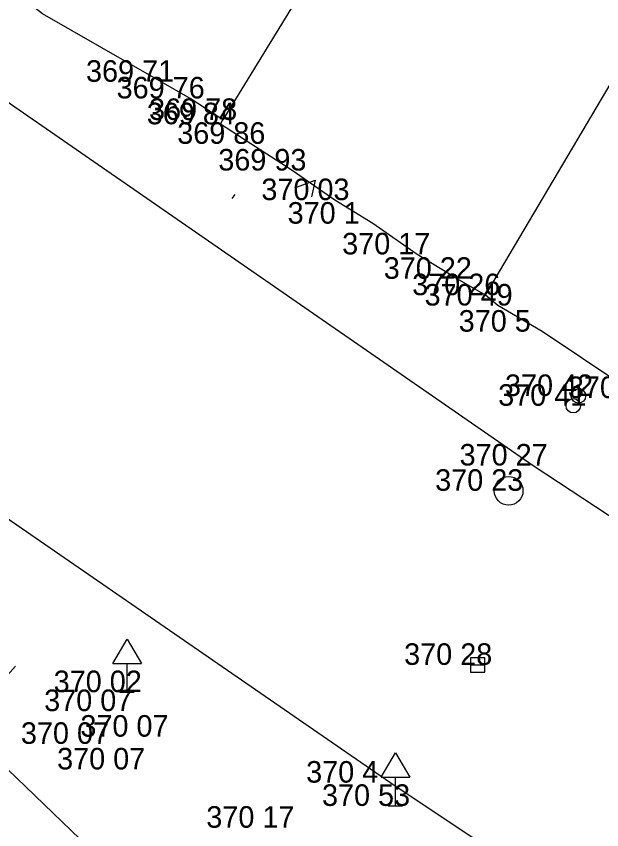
# Model space of a CAD drawing. Extents: x -688316 to -688024, y -973785 to -973591.
# Drawn here: x -688090.23 to -688069.85, y -973719.16 to -973690.84 of the extents above; entities that cross this region are included whole.
import ezdxf

# ---------------------------------------------------------------- set-up
doc = ezdxf.new("R2010")
doc.units = 0
for name, color, linetype in [('Vrstva 10', 7, 'Continuous'), ('Vrstva 27', 7, 'Continuous'), ('Vrstva 28_Verejne osvetleni', 7, 'Continuous'), ('Vrstva 3', 7, 'Continuous'), ('Vrstva 31', 7, 'Continuous'), ('Vrstva 34', 7, 'Continuous'), ('Vrstva 5', 7, 'Continuous'), ('Vrstva 50_telekomunikace cetin WMS', 7, 'Continuous'), ('Vrstva 6', 7, 'Continuous')]:
    doc.layers.add(name, color=color, linetype=linetype)

# ---------------------------------------------------------------- blocks, each defined once
blk = doc.blocks.new('DZ')
at = {"layer": 'Vrstva 34'}
for p, q in [((-5, 10), (0, 18.5)), ((0, 18.5), (5, 10)), ((-5, 10), (5, 10)), ((0, 0), (0, 10)), ((-2.49, 0), (2.49, 0))]:
    blk.add_line(p, q, dxfattribs=at)
blk = doc.blocks.new('VP')
at = {"layer": 'Vrstva 27'}
blk.add_line((-2.5, 0), (2.5, 0), dxfattribs=at)
blk.add_lwpolyline([(-2.5, -2.5), (2.5, -2.5), (2.5, 2.5), (-2.5, 2.5)], close=True, dxfattribs=at)
blk = doc.blocks.new('SV')
at = {"layer": 'Vrstva 28_Verejne osvetleni'}
blk.add_circle((0, 0), 2.5, dxfattribs=at)
blk = doc.blocks.new('SP')
at = {"layer": 'Vrstva 31'}
blk.add_circle((0, 0), 2.5, dxfattribs=at)
blk = doc.blocks.new('SAK')
at = {"layer": 'Vrstva 27'}
blk.add_circle((0, 0), 5, dxfattribs=at)

msp = doc.modelspace()

# ---------------------------------------------------------------- linework, layer by layer
at = {"layer": 'Vrstva 10'}
for p, q in [((-688093.66, -973691.65), (-688072.24, -973706.48)), ((-688077.23, -973717.52), (-688096.68, -973704.1)), ((-688072.24, -973706.48), (-688062.29, -973713.03)), ((-688069.37, -973722.73), (-688077.23, -973717.52))]:
    msp.add_line(p, q, dxfattribs=at)
at = {"layer": 'Vrstva 28_Verejne osvetleni'}
for p, q in [((-688080.528, -973696.814), (-688079.823, -973696.54)), ((-688079.823, -973696.54), (-688079.952, -973697.121))]:
    msp.add_line(p, q, dxfattribs=at)
at = {"layer": 'Vrstva 3'}
msp.add_lwpolyline([(-688071.97, -973725.53), (-688075.592, -973732.953), (-688087.068, -973720.398), (-688092.114, -973715.537), (-688090.26, -973713.47)], dxfattribs=at)
msp.add_lwpolyline([(-688071.97, -973725.53), (-688075.592, -973732.953), (-688087.068, -973720.398), (-688092.114, -973715.537), (-688090.26, -973713.47)], dxfattribs=at)
msp.add_lwpolyline([(-688071.97, -973725.53), (-688075.592, -973732.953), (-688087.068, -973720.398), (-688092.114, -973715.537), (-688090.26, -973713.47)], dxfattribs=at)
msp.add_lwpolyline([(-688071.97, -973725.53), (-688075.592, -973732.953), (-688087.068, -973720.398), (-688092.114, -973715.537), (-688090.26, -973713.47)], dxfattribs=at)
at = {"layer": 'Vrstva 5'}
for p, q in [((-688075.97, -973682.88), (-688083.04, -973694.45)), ((-688073.89, -973700.55), (-688068.56, -973691.52)), ((-688083.04, -973694.45), (-688084.17, -973693.7)), ((-688079.14, -973697.24), (-688080.63, -973696.21)), ((-688076.27, -973699.13), (-688077.82, -973698.06)), ((-688073.89, -973700.55), (-688074.88, -973699.98)), ((-688073.46, -973700.91), (-688073.89, -973700.55)), ((-688068.47, -973704.13), (-688071.92, -973701.82))]:
    msp.add_line(p, q, dxfattribs=at)
for points in [[(-688085.18, -973693.12), (-688089.31, -973690.76), (-688089.67, -973690.48), (-688089.75, -973690.26), (-688089.7, -973690), (-688088.85, -973688.72), (-688090.74, -973687.47), (-688091.1, -973687.21), (-688091.3, -973686.83), (-688085.88, -973677.49)], [(-688082.06, -973695.28), (-688083.12, -973694.6), (-688083.04, -973694.45)]]:
    msp.add_lwpolyline(points, dxfattribs=at)
at = {"layer": 'Vrstva 50_telekomunikace cetin WMS'}
msp.add_lwpolyline([(-688082.71, -973697.18), (-688082.61, -973697.05)], dxfattribs=at)
at = {"layer": 'Vrstva 6'}
for p, q in [((-688084.17, -973693.7), (-688085.18, -973693.12)), ((-688080.63, -973696.21), (-688082.06, -973695.28)), ((-688077.82, -973698.06), (-688079.14, -973697.24)), ((-688074.88, -973699.98), (-688076.27, -973699.13)), ((-688071.92, -973701.82), (-688073.46, -973700.91))]:
    msp.add_line(p, q, dxfattribs=at)

# ---------------------------------------------------------------- block references
at = {"layer": 'Vrstva 27', "xscale": 0.1, "yscale": 0.10000000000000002}
for name, p in [('SAK', (-688073.09, -973707.36)), ('VP', (-688074.17, -973713.42))]:
    msp.add_blockref(name, p, dxfattribs=at)
at = {"layer": 'Vrstva 28_Verejne osvetleni', "xscale": 0.1, "yscale": 0.10000000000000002}
msp.add_blockref('SV', (-688070.84, -973704.4), dxfattribs=at)
at = {"layer": 'Vrstva 31', "xscale": 0.1, "yscale": 0.10000000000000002}
msp.add_blockref('SP', (-688070.66, -973704.06), dxfattribs=at)
at = {"layer": 'Vrstva 34', "xscale": 0.1, "yscale": 0.10000000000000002}
for p in [(-688086.37, -973714.37), (-688086.37, -973714.37), (-688086.37, -973714.37), (-688086.37, -973714.37), (-688077.03, -973718.33), (-688077.03, -973718.33), (-688077.03, -973718.33), (-688077.03, -973718.33)]:
    msp.add_blockref('DZ', p, dxfattribs=at)

# ---------------------------------------------------------------- texts
at = {"layer": 'Vrstva 3'}
for s, p in [('369 71 ', (-688087.801, -973693.12)), ('369 71 ', (-688087.801, -973693.12)), ('369 71 ', (-688087.801, -973693.12)), ('369 71 ', (-688087.801, -973693.12)), ('369 71 ', (-688087.801, -973693.12)), ('369 71 ', (-688087.801, -973693.12)), ('369 71 ', (-688087.801, -973693.12)), ('369 76 ', (-688086.736, -973693.7)), ('369 76 ', (-688086.736, -973693.7)), ('369 76 ', (-688086.736, -973693.7)), ('369 76 ', (-688086.736, -973693.7)), ('369 76 ', (-688086.736, -973693.7)), ('369 76 ', (-688086.736, -973693.7)), ('369 76 ', (-688086.736, -973693.7)), ('369 78 ', (-688085.606, -973694.45)), ('369 78 ', (-688085.606, -973694.45)), ('369 78 ', (-688085.606, -973694.45)), ('369 78 ', (-688085.606, -973694.45)), ('369 78 ', (-688085.606, -973694.45)), ('369 78 ', (-688085.606, -973694.45)), ('369 78 ', (-688085.606, -973694.45)), ('369 84 ', (-688085.686, -973694.6)), ('369 84 ', (-688085.686, -973694.6)), ('369 84 ', (-688085.686, -973694.6)), ('369 84 ', (-688085.686, -973694.6)), ('369 84 ', (-688085.686, -973694.6)), ('369 84 ', (-688085.686, -973694.6)), ('369 84 ', (-688085.686, -973694.6)), ('369 86 ', (-688084.626, -973695.28)), ('369 86 ', (-688084.626, -973695.28)), ('369 86 ', (-688084.626, -973695.28)), ('369 86 ', (-688084.626, -973695.28)), ('369 86 ', (-688084.626, -973695.28)), ('369 86 ', (-688084.626, -973695.28)), ('369 86 ', (-688084.626, -973695.28)), ('369 93 ', (-688083.196, -973696.21)), ('369 93 ', (-688083.196, -973696.21)), ('369 93 ', (-688083.196, -973696.21)), ('369 93 ', (-688083.196, -973696.21)), ('369 93 ', (-688083.196, -973696.21)), ('369 93 ', (-688083.196, -973696.21)), ('369 93 ', (-688083.196, -973696.21)), ('370 03 ', (-688081.697, -973697.24)), ('370 03 ', (-688081.697, -973697.24)), ('370 03 ', (-688081.697, -973697.24)), ('370 03 ', (-688081.697, -973697.24)), ('370 03 ', (-688081.697, -973697.24)), ('370 03 ', (-688081.697, -973697.24)), ('370 03 ', (-688081.697, -973697.24)), ('370 1  ', (-688080.784, -973698.06)), ('370 1  ', (-688080.784, -973698.06)), ('370 1  ', (-688080.784, -973698.06)), ('370 1  ', (-688080.784, -973698.06)), ('370 1  ', (-688080.784, -973698.06)), ('370 1  ', (-688080.784, -973698.06)), ('370 1  ', (-688080.784, -973698.06)), ('370 17 ', (-688078.883, -973699.13)), ('370 17 ', (-688078.883, -973699.13)), ('370 17 ', (-688078.883, -973699.13)), ('370 17 ', (-688078.883, -973699.13)), ('370 17 ', (-688078.883, -973699.13)), ('370 17 ', (-688078.883, -973699.13)), ('370 17 ', (-688078.883, -973699.13)), ('370 22 ', (-688077.437, -973699.98)), ('370 22 ', (-688077.437, -973699.98)), ('370 22 ', (-688077.437, -973699.98)), ('370 22 ', (-688077.437, -973699.98)), ('370 22 ', (-688077.437, -973699.98)), ('370 22 ', (-688077.437, -973699.98)), ('370 22 ', (-688077.437, -973699.98)), ('370 26 ', (-688076.447, -973700.55)), ('370 26 ', (-688076.447, -973700.55)), ('370 26 ', (-688076.447, -973700.55)), ('370 26 ', (-688076.447, -973700.55)), ('370 26 ', (-688076.447, -973700.55)), ('370 26 ', (-688076.447, -973700.55)), ('370 26 ', (-688076.447, -973700.55)), ('370 49 ', (-688076.017, -973700.91)), ('370 49 ', (-688076.017, -973700.91)), ('370 49 ', (-688076.017, -973700.91)), ('370 49 ', (-688076.017, -973700.91)), ('370 49 ', (-688076.017, -973700.91)), ('370 49 ', (-688076.017, -973700.91)), ('370 49 ', (-688076.017, -973700.91)), ('370 5  ', (-688074.828, -973701.82)), ('370 5  ', (-688074.828, -973701.82)), ('370 5  ', (-688074.828, -973701.82)), ('370 5  ', (-688074.828, -973701.82)), ('370 5  ', (-688074.828, -973701.82)), ('370 5  ', (-688074.828, -973701.82)), ('370 5  ', (-688074.828, -973701.82)), ('370 42 ', (-688073.217, -973704.06)), ('370 42 ', (-688073.217, -973704.06)), ('370 42 ', (-688073.217, -973704.06)), ('370 42 ', (-688073.217, -973704.06)), ('370 42 ', (-688073.217, -973704.06)), ('370 42 ', (-688073.217, -973704.06)), ('370 42 ', (-688073.217, -973704.06)), ('370 57 ', (-688071.027, -973704.13)), ('370 57 ', (-688071.027, -973704.13)), ('370 57 ', (-688071.027, -973704.13)), ('370 57 ', (-688071.027, -973704.13)), ('370 57 ', (-688071.027, -973704.13)), ('370 57 ', (-688071.027, -973704.13)), ('370 57 ', (-688071.027, -973704.13)), ('370 41 ', (-688073.453, -973704.4)), ('370 41 ', (-688073.453, -973704.4)), ('370 41 ', (-688073.453, -973704.4)), ('370 41 ', (-688073.453, -973704.4)), ('370 41 ', (-688073.453, -973704.4)), ('370 41 ', (-688073.453, -973704.4)), ('370 41 ', (-688073.453, -973704.4)), ('370 27 ', (-688074.797, -973706.48)), ('370 27 ', (-688074.797, -973706.48)), ('370 27 ', (-688074.797, -973706.48)), ('370 27 ', (-688074.797, -973706.48)), ('370 27 ', (-688074.797, -973706.48)), ('370 27 ', (-688074.797, -973706.48)), ('370 27 ', (-688074.797, -973706.48)), ('370 23 ', (-688075.647, -973707.36)), ('370 23 ', (-688075.647, -973707.36)), ('370 23 ', (-688075.647, -973707.36)), ('370 23 ', (-688075.647, -973707.36)), ('370 23 ', (-688075.647, -973707.36)), ('370 23 ', (-688075.647, -973707.36)), ('370 23 ', (-688075.647, -973707.36)), ('370 28 ', (-688076.727, -973713.42)), ('370 28 ', (-688076.727, -973713.42)), ('370 28 ', (-688076.727, -973713.42)), ('370 28 ', (-688076.727, -973713.42)), ('370 28 ', (-688076.727, -973713.42)), ('370 28 ', (-688076.727, -973713.42)), ('370 28 ', (-688076.727, -973713.42)), ('370 02 ', (-688088.927, -973714.37)), ('370 02 ', (-688088.927, -973714.37)), ('370 02 ', (-688088.927, -973714.37)), ('370 02 ', (-688088.927, -973714.37)), ('370 02 ', (-688088.927, -973714.37)), ('370 02 ', (-688088.927, -973714.37)), ('370 02 ', (-688088.927, -973714.37)), ('370 07 ', (-688089.257, -973715.03)), ('370 07 ', (-688089.257, -973715.03)), ('370 07 ', (-688089.257, -973715.03)), ('370 07 ', (-688089.257, -973715.03)), ('370 07 ', (-688089.257, -973715.03)), ('370 07 ', (-688089.257, -973715.03)), ('370 07 ', (-688089.257, -973715.03)), ('370 07 ', (-688087.997, -973715.92)), ('370 07 ', (-688087.997, -973715.92)), ('370 07 ', (-688087.997, -973715.92)), ('370 07 ', (-688087.997, -973715.92)), ('370 07 ', (-688087.997, -973715.92)), ('370 07 ', (-688087.997, -973715.92)), ('370 07 ', (-688087.997, -973715.92)), ('370 07 ', (-688090.067, -973716.17)), ('370 07 ', (-688090.067, -973716.17)), ('370 07 ', (-688090.067, -973716.17)), ('370 07 ', (-688090.067, -973716.17)), ('370 07 ', (-688090.067, -973716.17)), ('370 07 ', (-688090.067, -973716.17)), ('370 07 ', (-688090.067, -973716.17)), ('370 07 ', (-688088.807, -973717.06)), ('370 07 ', (-688088.807, -973717.06)), ('370 07 ', (-688088.807, -973717.06)), ('370 07 ', (-688088.807, -973717.06)), ('370 07 ', (-688088.807, -973717.06)), ('370 07 ', (-688088.807, -973717.06)), ('370 07 ', (-688088.807, -973717.06)), ('370 4  ', (-688080.138, -973717.52)), ('370 4  ', (-688080.138, -973717.52)), ('370 4  ', (-688080.138, -973717.52)), ('370 4  ', (-688080.138, -973717.52)), ('370 4  ', (-688080.138, -973717.52)), ('370 4  ', (-688080.138, -973717.52)), ('370 4  ', (-688080.138, -973717.52)), ('370 53 ', (-688079.587, -973718.33)), ('370 53 ', (-688079.587, -973718.33)), ('370 53 ', (-688079.587, -973718.33)), ('370 53 ', (-688079.587, -973718.33)), ('370 53 ', (-688079.587, -973718.33)), ('370 53 ', (-688079.587, -973718.33)), ('370 53 ', (-688079.587, -973718.33)), ('370 17 ', (-688083.613, -973719.09)), ('370 17 ', (-688083.613, -973719.09)), ('370 17 ', (-688083.613, -973719.09)), ('370 17 ', (-688083.613, -973719.09)), ('370 17 ', (-688083.613, -973719.09)), ('370 17 ', (-688083.613, -973719.09)), ('370 17 ', (-688083.613, -973719.09))]:
    msp.add_text(s, height=0.75, dxfattribs=at).set_placement(p)

doc.saveas('drawing.dxf')
